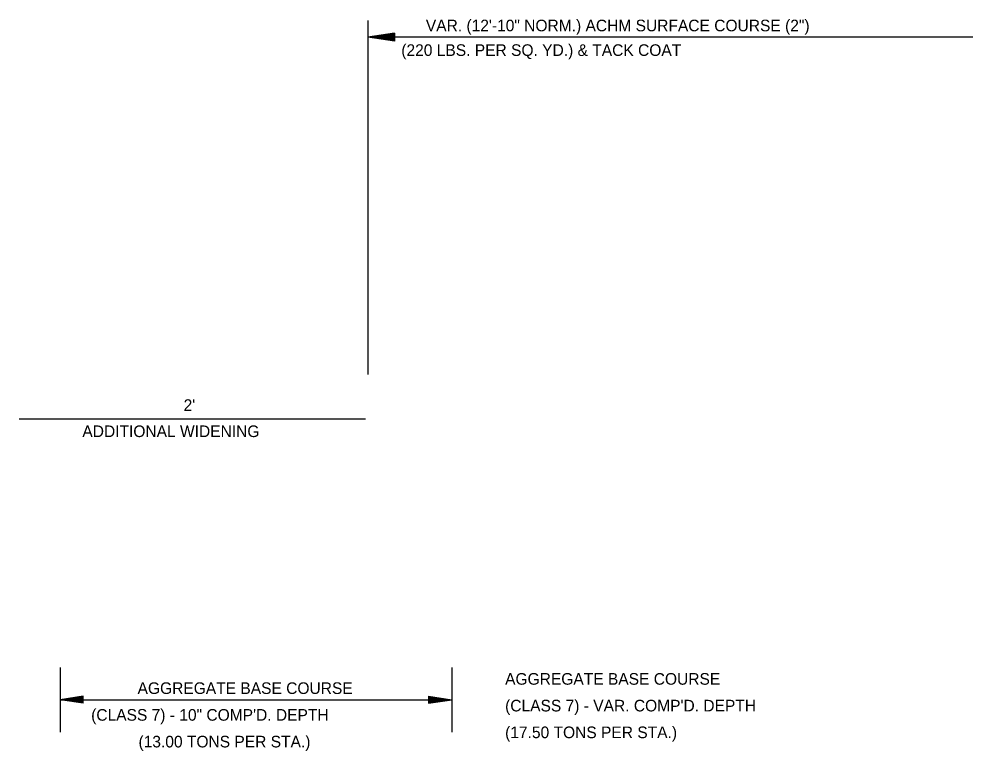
# Model space of a CAD drawing. Extents: x 1035 to 3550, y 35 to 1510.
# Drawn here: x 1034.8 to 1527, y 569.3 to 946.9 of the extents above; entities that cross this region are included whole.
import ezdxf

# ---------------------------------------------------------------- set-up
doc = ezdxf.new("R2010")
doc.units = 0
doc.layers.add('Default', color=7, linetype='Continuous')

msp = doc.modelspace()

# ---------------------------------------------------------------- linework, layer by layer
at = {"layer": 'Default'}
for p, q in [((1214.74, 946.14), (1214.74, 763.6)), ((1228.44, 939.67), (1214.74, 937.63)), ((1527, 937.63), (1214.74, 937.63)), ((1228.44, 935.57), (1214.74, 937.63)), ((1228.44, 939.34), (1217.01, 937.63)), ((1228.44, 935.92), (1217.01, 937.63)), ((1228.44, 938.99), (1219.38, 937.63)), ((1228.44, 936.26), (1219.38, 937.63)), ((1228.44, 938.66), (1221.66, 937.63)), ((1228.44, 936.62), (1221.66, 937.63)), ((1228.44, 938.27), (1223.98, 937.63)), ((1228.44, 936.95), (1223.98, 937.63)), ((1228.44, 937.96), (1226.25, 937.63)), ((1228.44, 937.3), (1226.25, 937.63)), ((1228.44, 939.67), (1228.44, 935.57)), ((1034.77, 740.65), (1213.46, 740.65)), ((1055.91, 612.37), (1055.91, 579.01)), ((1258.13, 612.37), (1258.13, 579.01)), ((1067.91, 597.49), (1055.91, 595.69)), ((1055.91, 595.69), (1258.13, 595.69)), ((1067.91, 593.89), (1055.91, 595.69)), ((1067.91, 597.19), (1057.91, 595.69)), ((1067.91, 594.19), (1057.91, 595.69)), ((1067.91, 596.88), (1059.98, 595.69)), ((1067.91, 594.5), (1059.98, 595.69)), ((1067.91, 596.58), (1061.98, 595.69)), ((1067.91, 594.8), (1061.98, 595.69)), ((1067.91, 596.28), (1064.01, 595.69)), ((1067.91, 595.11), (1064.01, 595.69)), ((1067.91, 595.97), (1066.01, 595.69)), ((1067.91, 595.41), (1066.01, 595.69)), ((1067.91, 593.89), (1067.91, 597.49)), ((1246.13, 597.49), (1258.13, 595.69)), ((1246.13, 597.49), (1246.13, 593.89)), ((1246.13, 597.19), (1256.13, 595.69)), ((1246.13, 596.88), (1254.06, 595.69)), ((1246.13, 596.58), (1252.06, 595.69)), ((1246.13, 596.27), (1250.03, 595.69)), ((1246.13, 595.97), (1248.03, 595.69)), ((1246.13, 593.89), (1258.13, 595.69)), ((1246.13, 595.1), (1250.03, 595.69)), ((1246.13, 594.5), (1254.06, 595.69)), ((1246.13, 594.19), (1256.13, 595.69)), ((1246.13, 594.8), (1252.06, 595.69)), ((1246.13, 595.41), (1248.03, 595.69))]:
    msp.add_line(p, q, dxfattribs=at)

# ---------------------------------------------------------------- texts
for s, p in [('VAR. (12\'-10" NORM.) ACHM SURFACE COURSE (2")', (1244.68, 940.6)), ('(220 LBS. PER SQ. YD.) & TACK COAT', (1232.02, 927.9)), ("2'", (1119.68, 744.73)), ('ADDITIONAL WIDENING', (1067.43, 731.23)), ('AGGREGATE BASE COURSE', (1285.59, 603.45)), ('AGGREGATE BASE COURSE', (1095.92, 598.67)), ("(CLASS 7) - VAR. COMP'D. DEPTH", (1285.59, 589.66)), ('(CLASS 7) - 10" COMP\'D. DEPTH', (1071.97, 584.88)), ('(17.50 TONS PER STA.)', (1285.59, 575.87)), ('(13.00 TONS PER STA.)', (1096.4, 571.09))]:
    msp.add_text(s, height=6, dxfattribs=at).set_placement(p)

doc.saveas('drawing.dxf')
